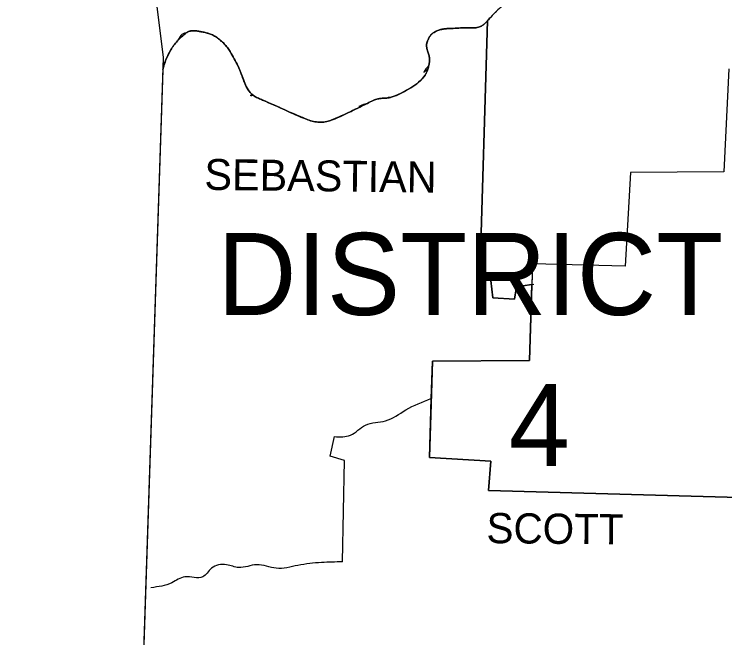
# Model space of a CAD drawing. Extents: x -13171 to 18763, y -8840 to 11152.
# Drawn here: x 10745 to 11711, y 7898 to 8746 of the extents above; entities that cross this region are included whole.
import ezdxf

# ---------------------------------------------------------------- set-up
doc = ezdxf.new("R2010")
doc.units = 0
for name, color, linetype in [('Level 1', 7, 'Continuous'), ('Level 2', 7, 'Continuous'), ('Level 3', 7, 'Continuous'), ('Level 48', 7, 'Continuous')]:
    doc.layers.add(name, color=color, linetype=linetype)

msp = doc.modelspace()

# ---------------------------------------------------------------- linework, layer by layer
at = {"layer": 'Level 1'}
msp.add_line((11311.888127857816, 8223.111308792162), (11312.3324662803, 8223.320542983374), dxfattribs=at)
for points in [[(10745.390580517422, 10312.988270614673), (10947.920791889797, 8686.876140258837), (10859.864178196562, 6032.458444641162)], [(11388.567808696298, 8736.575450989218), (11378.419791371, 8387.483654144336), (11393.095893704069, 8383.570026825), (11396.031114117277, 8360.08826321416), (11425.383318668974, 8358.131449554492), (11428.318539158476, 8374.764365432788), (11451.80030269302, 8378.67799267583)], [(11716.948550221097, 8671.221631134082), (11710.099702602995, 8531.309456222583), (11582.906816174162, 8530.331049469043), (11576.057968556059, 8403.138163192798), (11449.843489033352, 8406.073383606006), (11445.929861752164, 8274.966870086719), (11313.844941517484, 8273.988463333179), (11309.931314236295, 8142.881949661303), (11393.095893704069, 8137.989915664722), (11390.160673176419, 8097.875236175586), (11827.900316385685, 8085.771835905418)], [(11191.544089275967, 8001.0129612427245), (11194.479309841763, 8138.9683225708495), (11174.91117343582, 8144.838763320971), (11180.781614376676, 8171.255747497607)]]:
    msp.add_lwpolyline(points, dxfattribs=at)
for points in [[(11454.735523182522, 8917.780149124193), (11455.612357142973, 8912.663859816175), (11455.98488757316, 8907.452184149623), (11454.735523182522, 8897.233606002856), (11452.950627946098, 8891.815859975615), (11450.895159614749, 8886.475128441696), (11448.803059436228, 8881.13239818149), (11446.908268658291, 8875.70865597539), (11442.016234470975, 8857.118926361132), (11442.023444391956, 8851.055816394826), (11443.52192513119, 8844.908468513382), (11445.001365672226, 8838.75130696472), (11445.261973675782, 8835.692303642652), (11444.951454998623, 8832.658755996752), (11441.344939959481, 8822.595474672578), (11436.145793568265, 8813.090619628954), (11433.14169039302, 8808.983337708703), (11429.65109198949, 8805.249909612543), (11426.228022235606, 8801.523209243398), (11423.426505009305, 8797.436110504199), (11422.612506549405, 8792.784643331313), (11423.493055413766, 8787.660128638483), (11424.340329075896, 8782.531570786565), (11423.426505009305, 8777.867974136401), (11421.86730924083, 8775.122246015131), (11420.243552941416, 8772.4075669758), (11416.774155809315, 8767.110635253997), (11412.961907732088, 8762.055737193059), (11408.750402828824, 8757.321431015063), (11393.095893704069, 8741.666921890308), (11386.858936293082, 8734.618487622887), (11383.480516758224, 8731.392237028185), (11381.552216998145, 8730.044901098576), (11380.506531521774, 8729.461592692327), (11379.398198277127, 8728.94763340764), (11373.352562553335, 8727.29911046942), (11367.233335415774, 8726.893252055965), (11361.081497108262, 8727.02538090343), (11358.006155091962, 8727.072978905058), (11354.938027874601, 8726.990819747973), (11344.665047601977, 8726.513200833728), (11334.391484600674, 8726.012412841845), (11329.067462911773, 8725.490061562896), (11323.889080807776, 8724.384519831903), (11318.82526482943, 8722.38071269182), (11316.326608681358, 8720.943498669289), (11313.844941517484, 8719.163565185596), (11310.609534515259, 8715.935386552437), (11308.365609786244, 8712.349359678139), (11306.904537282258, 8708.501409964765), (11306.017686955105, 8704.487462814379), (11306.256050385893, 8698.874063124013), (11307.898550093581, 8693.225334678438), (11309.579025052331, 8687.581831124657), (11309.931314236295, 8681.984106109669), (11309.018511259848, 8676.43069044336), (11307.614201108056, 8670.957855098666), (11302.104059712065, 8660.459156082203), (11292.458280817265, 8650.956737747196), (11281.557516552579, 8643.826240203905), (11270.524128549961, 8637.809323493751), (11259.054159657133, 8633.063765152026), (11253.2193963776, 8631.832798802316), (11247.203108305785, 8631.353586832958), (11241.241904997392, 8630.7510571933), (11235.572396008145, 8629.15013783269), (11227.440015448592, 8625.385856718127), (11219.402375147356, 8621.412684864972), (11211.377889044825, 8617.394612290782), (11203.284971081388, 8613.49562901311), (11173.932766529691, 8600.776340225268), (11166.283379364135, 8598.962229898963), (11158.23528129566, 8598.846966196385), (11150.208671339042, 8600.185592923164), (11142.62374850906, 8602.733153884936), (11113.271543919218, 8615.452442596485), (11086.854559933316, 8627.193324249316), (11081.360377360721, 8629.498790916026), (11075.895197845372, 8631.906088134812), (11070.77306355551, 8634.892223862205), (11068.438776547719, 8636.751421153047), (11067.345502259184, 8637.798638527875), (11066.30801665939, 8638.934206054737), (11060.75323199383, 8647.416196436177), (11056.896773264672, 8656.60846252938), (11053.587707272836, 8666.013863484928), (11051.778779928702, 8670.641133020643), (11049.675100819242, 8675.135258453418), (11044.466597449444, 8684.975578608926), (11038.912625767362, 8694.703394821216), (11035.152842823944, 8700.255734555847), (11030.870011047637, 8705.305141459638), (11025.961054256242, 8709.945709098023), (11023.239567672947, 8712.142082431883), (11020.322896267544, 8714.271531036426), (11014.883142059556, 8717.379374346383), (11009.27083741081, 8719.504022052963), (11003.558723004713, 8720.969237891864), (10997.819539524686, 8722.098785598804), (10993.203239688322, 8722.872284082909), (10988.454518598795, 8723.159201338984), (10983.74087555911, 8722.426707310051), (10981.449551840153, 8721.511671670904), (10979.22980987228, 8720.141971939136), (10967.173548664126, 8709.249197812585), (10958.160238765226, 8697.140161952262), (10951.715223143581, 8684.01835777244), (10949.307495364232, 8677.141259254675), (10947.363844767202, 8670.087278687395)], [(11180.781614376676, 8171.255747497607), (11202.306564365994, 8173.212561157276), (11222.853107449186, 8186.910256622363), (11250.248498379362, 8192.78069744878), (11277.64388927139, 8207.456799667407), (11311.888127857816, 8223.111308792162)], [(11191.544089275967, 8001.0129612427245), (11163.170291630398, 8000.034554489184), (11130.882866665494, 7996.120927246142), (11101.530662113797, 7992.207299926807), (11075.113678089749, 7997.099333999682), (11050.65350757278, 7993.185706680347), (11034.020591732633, 7997.099333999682), (11013.474048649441, 7992.207299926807), (11001.733166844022, 7980.466418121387), (10977.27299625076, 7980.466418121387), (10959.66167354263, 7972.639163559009), (10931.287875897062, 7965.7903157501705)]]:
    msp.add_spline(points, degree=3, dxfattribs=at)
at = {"layer": 'Level 48'}
for p, q in [((11393.09589370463, 8741.666921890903), (11396.970801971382, 8745.614881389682)), ((11396.970801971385, 8745.614881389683), (11400.921270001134, 8749.491502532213)), ((11388.566359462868, 8736.525597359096), (11386.858936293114, 8734.618487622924)), ((11389.202136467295, 8737.260691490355), (11390.988122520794, 8739.334822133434)), ((10983.74087555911, 8722.426707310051), (10982.273637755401, 8721.90200086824)), ((10983.830943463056, 8722.45219376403), (10983.74087555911, 8722.426707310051)), ((10990.764458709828, 8723.116008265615), (10988.454518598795, 8723.159201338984)), ((10994.277470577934, 8722.704073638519), (10993.987864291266, 8722.749878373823)), ((11344.665047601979, 8726.51320083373), (11339.925173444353, 8726.285509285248)), ((11014.910015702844, 8717.366704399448), (11014.883142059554, 8717.379374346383)), ((11023.239567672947, 8712.142082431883), (11021.771207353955, 8713.24507731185)), ((11313.500243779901, 8718.882213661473), (11311.456950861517, 8716.921028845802)), ((11313.844941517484, 8719.163565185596), (11313.500243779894, 8718.882213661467)), ((11315.146004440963, 8720.145754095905), (11313.844941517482, 8719.163565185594)), ((11025.961054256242, 8709.945709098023), (11024.1626761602, 8711.41853658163)), ((11026.320892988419, 8709.638042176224), (11025.961054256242, 8709.945709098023)), ((11034.476175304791, 8701.145001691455), (11031.248327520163, 8704.908589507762)), ((11306.66476992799, 8707.68224713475), (11306.034421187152, 8704.62108130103)), ((10958.160238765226, 8697.140161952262), (10951.715223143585, 8684.018357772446)), ((10958.229654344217, 8697.259020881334), (10958.160238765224, 8697.14016195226)), ((11035.152842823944, 8700.255734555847), (11034.476175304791, 8701.145001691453)), ((11305.861066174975, 8701.63320490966), (11305.957197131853, 8700.355582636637)), ((10951.715223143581, 8684.01835777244), (10949.830139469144, 8678.83229983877)), ((10947.3638447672, 8670.087278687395), (10913.67835443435, 7654.656888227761)), ((11055.218795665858, 8661.405318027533), (11054.050759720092, 8664.742938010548)), ((11068.438776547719, 8636.751421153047), (11067.345502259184, 8637.798638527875)), ((11281.557516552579, 8643.826240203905), (11270.524128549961, 8637.809323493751)), ((11227.440015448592, 8625.385856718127), (11227.31857751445, 8625.325954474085)), ((11237.412740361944, 8629.86321686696), (11236.800737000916, 8629.64627560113)), ((11241.241904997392, 8630.7510571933), (11237.412740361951, 8629.863216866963)), ((11247.203108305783, 8631.353586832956), (11241.820288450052, 8630.82033611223)), ((11253.21939637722, 8631.832798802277), (11247.203108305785, 8631.353586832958)), ((11259.054159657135, 8633.063765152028), (11256.932204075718, 8632.46590624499)), ((11219.402375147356, 8621.412684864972), (11219.262333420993, 8621.342881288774)), ((11204.547430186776, 8614.097472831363), (11203.284971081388, 8613.49562901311)), ((11160.667378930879, 8598.700472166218), (11160.074025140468, 8598.722407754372)), ((11166.283379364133, 8598.962229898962), (11160.66737893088, 8598.70047216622)), ((11396.031114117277, 8360.08826321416), (11393.095893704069, 8383.570026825)), ((11449.011843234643, 8378.213249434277), (11428.318539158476, 8374.764365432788)), ((11449.011843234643, 8378.213249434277), (11445.929861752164, 8274.966870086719))]:
    msp.add_line(p, q, dxfattribs=at)
for points in [[(10883.435220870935, 9204.629854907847), (10947.920791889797, 8686.876140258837), (10947.3638447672, 8670.087278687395)], [(11393.095893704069, 8383.570026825), (11378.419791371, 8387.483654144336), (11388.56635946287, 8736.525597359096)], [(11716.948550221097, 8671.221631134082), (11710.099702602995, 8531.309456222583), (11582.906816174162, 8530.331049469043), (11576.057968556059, 8403.138163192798), (11449.843489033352, 8406.073383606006), (11449.011843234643, 8378.213249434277)], [(11827.900316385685, 8085.771835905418), (11390.160673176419, 8097.875236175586), (11393.095893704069, 8137.989915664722), (11309.931314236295, 8142.881949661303), (11312.325830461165, 8223.098243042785), (11313.844941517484, 8273.988463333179), (11445.929861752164, 8274.966870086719), (11449.011843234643, 8378.213249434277)], [(11428.318539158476, 8374.764365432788), (11425.383318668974, 8358.131449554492), (11396.031114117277, 8360.08826321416)], [(11445.929861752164, 8274.966870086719), (11313.844941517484, 8273.988463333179), (11312.325830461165, 8223.098243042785), (11309.931314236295, 8142.881949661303), (11393.095893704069, 8137.989915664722)], [(11393.095893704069, 8137.989915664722), (11390.160673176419, 8097.875236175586), (11827.900316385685, 8085.771835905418)]]:
    msp.add_lwpolyline(points, dxfattribs=at)
for points in [[(11390.988122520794, 8739.334822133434), (11393.095893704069, 8741.666921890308), (11393.095893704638, 8741.666921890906)], [(11256.932204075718, 8632.46590624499), (11259.054159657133, 8633.063765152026), (11270.524128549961, 8637.809323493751), (11281.557516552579, 8643.826240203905), (11292.458280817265, 8650.956737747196), (11302.104059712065, 8660.459156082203), (11307.614201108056, 8670.957855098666), (11309.018511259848, 8676.43069044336), (11309.931314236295, 8681.984106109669), (11309.579025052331, 8687.581831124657), (11307.898550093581, 8693.225334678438), (11306.256050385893, 8698.874063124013), (11306.017686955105, 8704.487462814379), (11306.904537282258, 8708.501409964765), (11308.365609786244, 8712.349359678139), (11310.609534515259, 8715.935386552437), (11313.844941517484, 8719.163565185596), (11316.326608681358, 8720.943498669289), (11318.82526482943, 8722.38071269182), (11323.889080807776, 8724.384519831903), (11329.067462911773, 8725.490061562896), (11334.391484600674, 8726.012412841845), (11344.665047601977, 8726.513200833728), (11354.938027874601, 8726.990819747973), (11358.006155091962, 8727.072978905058), (11361.081497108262, 8727.02538090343), (11367.233335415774, 8726.893252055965), (11373.352562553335, 8727.29911046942), (11379.398198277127, 8728.94763340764), (11380.506531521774, 8729.461592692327), (11381.552216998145, 8730.044901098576), (11383.480516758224, 8731.392237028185), (11386.858936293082, 8734.618487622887), (11388.566359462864, 8736.525597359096)], [(10947.363844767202, 8670.087278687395), (10949.307495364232, 8677.141259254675), (10951.715223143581, 8684.01835777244), (10958.160238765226, 8697.140161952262), (10967.173548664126, 8709.249197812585), (10979.22980987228, 8720.141971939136), (10981.449551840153, 8721.511671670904), (10983.74087555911, 8722.426707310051), (10988.454518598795, 8723.159201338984), (10993.203239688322, 8722.872284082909), (10997.819539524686, 8722.098785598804), (11003.558723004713, 8720.969237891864), (11009.27083741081, 8719.504022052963), (11014.883142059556, 8717.379374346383), (11020.322896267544, 8714.271531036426), (11023.239567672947, 8712.142082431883), (11025.961054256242, 8709.945709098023), (11030.870011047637, 8705.305141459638), (11035.152842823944, 8700.255734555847), (11038.912625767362, 8694.703394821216), (11044.466597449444, 8684.975578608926), (11049.675100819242, 8675.135258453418), (11051.778779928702, 8670.641133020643), (11053.587707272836, 8666.013863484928), (11056.896773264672, 8656.60846252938), (11060.75323199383, 8647.416196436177), (11066.30801665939, 8638.934206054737), (11067.345502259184, 8637.798638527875), (11068.438776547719, 8636.751421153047), (11070.77306355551, 8634.892223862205), (11071.161602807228, 8634.624828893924)], [(10993.987864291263, 8722.749878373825), (10993.203239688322, 8722.872284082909), (10990.76445870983, 8723.116008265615)], [(10979.22980987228, 8720.141971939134), (10979.22980987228, 8720.141971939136), (10967.173548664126, 8709.249197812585)], [(11004.426463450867, 8720.780023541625), (11003.558723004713, 8720.969237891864), (10999.290877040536, 8721.820989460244)], [(11309.018511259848, 8676.43069044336), (11307.614201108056, 8670.957855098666), (11307.614201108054, 8670.957855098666)], [(11070.607308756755, 8635.008595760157), (11068.438776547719, 8636.751421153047), (11068.438776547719, 8636.751421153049)], [(11270.524128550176, 8637.809323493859), (11270.524128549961, 8637.809323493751), (11261.881585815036, 8634.031948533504)], [(11071.161602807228, 8634.624828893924), (11075.895197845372, 8631.906088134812), (11081.360377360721, 8629.498790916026), (11086.854559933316, 8627.193324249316), (11113.271543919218, 8615.452442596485), (11142.62374850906, 8602.733153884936), (11150.208671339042, 8600.185592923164), (11158.23528129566, 8598.846966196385), (11166.283379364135, 8598.962229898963), (11173.932766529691, 8600.776340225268), (11203.284971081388, 8613.49562901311), (11211.377889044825, 8617.394612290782), (11219.402375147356, 8621.412684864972), (11227.440015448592, 8625.385856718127), (11235.572396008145, 8629.15013783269), (11241.241904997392, 8630.7510571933), (11247.203108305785, 8631.353586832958), (11253.2193963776, 8631.832798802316), (11256.932204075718, 8632.46590624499)], [(11075.895197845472, 8631.906088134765), (11075.895197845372, 8631.906088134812), (11071.161602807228, 8634.624828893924)], [(11081.261480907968, 8629.540647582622), (11075.895197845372, 8631.906088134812), (11075.895197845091, 8631.906088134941)], [(11241.82027800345, 8630.820427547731), (11241.241904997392, 8630.7510571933), (11241.24190499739, 8630.751057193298)], [(11256.932204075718, 8632.46590624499), (11253.2193963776, 8631.832798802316), (11253.219396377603, 8631.832798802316)], [(11261.88158581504, 8634.031948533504), (11259.054159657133, 8633.063765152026), (11259.054159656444, 8633.06376515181)], [(11227.31857751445, 8625.325954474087), (11219.402375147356, 8621.412684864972), (11219.402375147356, 8621.412684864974)]]:
    msp.add_spline(points, degree=3, dxfattribs=at)
for points, degree in [([(11386.858936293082, 8734.618487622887), (11385.811639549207, 8733.46457362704), (11384.683578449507, 8732.396329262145), (11383.480516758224, 8731.392237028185), (11382.87469825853, 8730.886612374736), (11382.226084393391, 8730.451092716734), (11381.552216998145, 8730.044901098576), (11381.209213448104, 8729.838146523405), (11380.861614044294, 8729.646692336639), (11380.506531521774, 8729.461592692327)], 3), ([(11388.566359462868, 8736.525597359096), (11388.779045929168, 8736.770009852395), (11388.990815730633, 8737.01517928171), (11389.202136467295, 8737.260691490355)], 2), ([(10988.454518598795, 8723.159201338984), (10986.900491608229, 8723.14464158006), (10985.361633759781, 8722.882017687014), (10983.830943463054, 8722.452193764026)], 2), ([(10999.290877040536, 8721.820989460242), (10998.800822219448, 8721.914695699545), (10998.310407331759, 8722.007231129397), (10997.819539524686, 8722.098785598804), (10996.640799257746, 8722.31863896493), (10995.461191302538, 8722.516061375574), (10994.277470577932, 8722.704073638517)], 3), ([(11322.981121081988, 8724.103617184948), (11321.55252969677, 8723.635667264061), (11320.175588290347, 8723.060787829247), (11318.82526482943, 8722.38071269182), (11318.223869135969, 8722.077826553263), (11317.644026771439, 8721.753052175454), (11317.073130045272, 8721.408242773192)], 3), ([(11325.439122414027, 8724.803957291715), (11324.921141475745, 8724.675162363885), (11324.404738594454, 8724.534774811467), (11323.889080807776, 8724.384519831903), (11323.583990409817, 8724.295621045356), (11323.281414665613, 8724.201981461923), (11322.981121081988, 8724.103617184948)], 3), ([(11339.925173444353, 8726.285509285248), (11338.080583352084, 8726.195489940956), (11336.236056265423, 8726.104119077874), (11334.391484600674, 8726.012412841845), (11332.610443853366, 8725.923865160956), (11330.839998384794, 8725.710798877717), (11329.067462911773, 8725.490061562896), (11327.842717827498, 8725.337541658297), (11326.636702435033, 8725.101733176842), (11325.439122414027, 8724.803957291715)], 3), ([(11354.938027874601, 8726.990819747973), (11351.51293668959, 8726.835016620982), (11348.089313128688, 8726.6746132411), (11344.665047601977, 8726.513200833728)], 2), ([(11356.118650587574, 8727.039846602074), (11355.72502410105, 8727.02585787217), (11355.331466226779, 8727.008716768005), (11354.938027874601, 8726.990819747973)], 2), ([(11361.081497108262, 8727.02538090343), (11360.056395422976, 8727.043246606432), (11359.031236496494, 8727.067231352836), (11358.006155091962, 8727.072978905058), (11357.3769502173, 8727.076506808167), (11356.747712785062, 8727.062202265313), (11356.118650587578, 8727.039846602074)], 3), ([(11367.06802081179, 8726.896414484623), (11365.072535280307, 8726.935063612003), (11363.077201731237, 8726.99059931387), (11361.081497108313, 8727.02538090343)], 2), ([(11380.133985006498, 8729.274569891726), (11379.893221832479, 8729.158381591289), (11379.649308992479, 8729.049785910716), (11379.398198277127, 8728.94763340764), (11377.442343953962, 8728.151986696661), (11375.434498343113, 8727.584323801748), (11373.352562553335, 8727.29911046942), (11371.315045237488, 8727.019982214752), (11369.277074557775, 8726.854653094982), (11367.233335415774, 8726.893252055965), (11367.17823042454, 8726.894292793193), (11367.123125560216, 8726.895347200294), (11367.06802081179, 8726.896414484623)], 3), ([(11380.506531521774, 8729.461592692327), (11380.382819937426, 8729.397103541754), (11380.258825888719, 8729.334816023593), (11380.133985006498, 8729.274569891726)], 2), ([(10982.273637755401, 8721.902000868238), (10981.996616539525, 8721.782277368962), (10981.72296307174, 8721.652225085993), (10981.449551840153, 8721.511671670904), (10980.665944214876, 8721.108839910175), (10979.93665003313, 8720.666653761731), (10979.22980987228, 8720.141971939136)], 3), ([(11009.975086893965, 8719.293036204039), (11009.7412778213, 8719.365653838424), (11009.506543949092, 8719.435984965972), (11009.27083741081, 8719.504022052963), (11007.662321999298, 8719.968322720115), (11006.054293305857, 8720.410750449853), (11004.426463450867, 8720.780023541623)], 3), ([(11014.883142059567, 8717.379374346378), (11014.883142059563, 8717.37937434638), (11014.88314205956, 8717.379374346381), (11014.883142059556, 8717.379374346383), (11013.282951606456, 8718.133139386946), (11011.65282846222, 8718.771954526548), (11009.975086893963, 8719.293036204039)], 3), ([(11021.771207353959, 8713.245077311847), (11021.293832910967, 8713.592992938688), (11020.811433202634, 8713.934625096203), (11020.322896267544, 8714.271531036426), (11018.60568972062, 8715.455754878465), (11016.803572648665, 8716.47317153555), (11014.910015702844, 8717.366704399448)], 3), ([(11308.365609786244, 8712.349359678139), (11307.772733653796, 8711.093881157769), (11307.31425945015, 8709.829335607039), (11306.904537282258, 8708.501409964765), (11306.820397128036, 8708.228708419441), (11306.74032335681, 8707.955691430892), (11306.664769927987, 8707.682247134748)], 3), ([(11310.609534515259, 8715.935386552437), (11309.704850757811, 8714.822542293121), (11308.974938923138, 8713.639679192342), (11308.365609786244, 8712.349359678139)], 2), ([(11311.456950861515, 8716.921028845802), (11311.167177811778, 8716.60281531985), (11310.885179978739, 8716.274455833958), (11310.609534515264, 8715.935386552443)], 2), ([(11317.073130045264, 8721.408242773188), (11316.822925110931, 8721.257124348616), (11316.574438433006, 8721.102157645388), (11316.326608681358, 8720.943498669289), (11315.92446145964, 8720.686046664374), (11315.531894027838, 8720.420667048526), (11315.146004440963, 8720.145754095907)], 3), ([(10967.173548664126, 8709.249197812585), (10963.770652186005, 8705.509767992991), (10960.773110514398, 8701.603051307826), (10958.229654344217, 8697.259020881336)], 2), ([(11024.1626761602, 8711.41853658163), (11023.856731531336, 8711.66144533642), (11023.549013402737, 8711.902407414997), (11023.239567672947, 8712.142082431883)], 2), ([(11031.248327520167, 8704.908589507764), (11031.12300360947, 8705.04133591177), (11030.996901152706, 8705.17351638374), (11030.870011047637, 8705.305141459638), (11029.410762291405, 8706.818842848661), (11027.908411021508, 8708.269007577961), (11026.320892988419, 8709.638042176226)], 3), ([(11306.034421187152, 8704.621081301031), (11306.02868362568, 8704.576563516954), (11306.023104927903, 8704.532024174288), (11306.017686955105, 8704.487462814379), (11305.903994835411, 8703.552375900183), (11305.835195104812, 8702.589619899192), (11305.861066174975, 8701.63320490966)], 3), ([(11038.912625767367, 8694.70339482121), (11038.912625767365, 8694.703394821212), (11038.912625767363, 8694.703394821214), (11038.912625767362, 8694.703394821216), (11037.768805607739, 8696.627274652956), (11036.492423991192, 8698.455844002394), (11035.152842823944, 8700.255734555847)], 3), ([(11044.466597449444, 8684.975578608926), (11042.677661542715, 8688.255501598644), (11040.823381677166, 8691.489546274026), (11038.912625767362, 8694.703394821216)], 2), ([(11305.957197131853, 8700.35558263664), (11306.021293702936, 8699.853950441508), (11306.118421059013, 8699.358409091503), (11306.256050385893, 8698.874063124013), (11306.744979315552, 8697.15342144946), (11307.246740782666, 8695.44071692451), (11307.750881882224, 8693.727105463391)], 3), ([(11307.750881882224, 8693.727105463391), (11307.800085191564, 8693.559859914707), (11307.849311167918, 8693.39260572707), (11307.898550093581, 8693.225334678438), (11308.452832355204, 8691.342365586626), (11309.030542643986, 8689.473803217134), (11309.579025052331, 8687.581831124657), (11309.733977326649, 8687.047328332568), (11309.844335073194, 8686.500335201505), (11309.918076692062, 8685.946973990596)], 3), ([(11051.453355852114, 8671.396842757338), (11050.8985711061, 8672.66096954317), (11050.301373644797, 8673.904290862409), (11049.675100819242, 8675.135258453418), (11047.990823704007, 8678.445781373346), (11046.244689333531, 8681.715537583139), (11044.466597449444, 8684.975578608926)], 3), ([(11309.918076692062, 8685.946973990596), (11310.092963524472, 8684.634613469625), (11310.061900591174, 8683.286435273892), (11309.931314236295, 8681.984106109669), (11309.84562005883, 8681.1294836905), (11309.727472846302, 8680.276811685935), (11309.587201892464, 8679.425337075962)], 3), ([(10949.830139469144, 8678.832299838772), (10949.647233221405, 8678.271789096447), (10949.472368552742, 8677.708431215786), (10949.307495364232, 8677.141259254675), (10948.626032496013, 8674.79699312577), (10947.939073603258, 8672.457426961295), (10947.363844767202, 8670.087278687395)], 3), ([(11309.587201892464, 8679.425337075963), (11309.422552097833, 8678.425877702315), (11309.22742016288, 8677.428068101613), (11309.018511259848, 8676.43069044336)], 2), ([(11054.050759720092, 8664.742938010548), (11053.898448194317, 8665.167267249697), (11053.744301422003, 8665.590975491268), (11053.587707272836, 8666.013863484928), (11053.012534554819, 8667.567137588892), (11052.423724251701, 8669.113745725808), (11051.778779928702, 8670.641133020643), (11051.672047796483, 8670.893901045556), (11051.56353827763, 8671.145782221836), (11051.453355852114, 8671.396842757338)], 3), ([(11307.614201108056, 8670.957855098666), (11306.410993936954, 8667.159144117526), (11304.561916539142, 8663.704587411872), (11302.104059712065, 8660.459156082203), (11299.29724867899, 8656.752954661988), (11296.155441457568, 8653.617002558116), (11292.458280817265, 8650.956737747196), (11289.415031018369, 8648.76698968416), (11286.35448179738, 8646.709973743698), (11283.176534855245, 8644.78768730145)], 3), ([(11058.225216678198, 8653.141028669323), (11057.76158514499, 8654.287854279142), (11057.319273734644, 8655.443077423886), (11056.896773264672, 8656.60846252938), (11056.319127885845, 8658.201784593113), (11055.770617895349, 8659.804257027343), (11055.21879566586, 8661.40531802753)], 3), ([(11067.345502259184, 8637.798638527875), (11066.983101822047, 8638.163117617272), (11066.63901627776, 8638.537928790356), (11066.30801665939, 8638.934206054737), (11064.126159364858, 8641.5463554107), (11062.225429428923, 8644.35095084), (11060.75323199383, 8647.416196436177), (11059.845435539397, 8649.306309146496), (11059.00515867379, 8651.211786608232), (11058.225216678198, 8653.141028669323)], 3), ([(11283.176534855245, 8644.78768730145), (11282.640364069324, 8644.463366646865), (11282.100851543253, 8644.142881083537), (11281.557516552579, 8643.826240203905)], 2), ([(11071.161602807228, 8634.624828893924), (11071.031650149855, 8634.71331842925), (11070.902286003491, 8634.80259752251), (11070.77306355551, 8634.892223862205), (11070.717579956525, 8634.930706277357), (11070.662332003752, 8634.969501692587), (11070.607308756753, 8635.008595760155)], 3), ([(11086.849366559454, 8627.195587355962), (11085.030369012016, 8627.98818652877), (11083.18810776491, 8628.725886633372), (11081.360377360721, 8629.498790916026), (11081.32740678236, 8629.512733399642), (11081.294441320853, 8629.526685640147), (11081.261480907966, 8629.540647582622)], 3), ([(11113.271543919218, 8615.452442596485), (11104.458148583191, 8619.350029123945), (11095.688198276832, 8623.343605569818), (11086.854559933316, 8627.193324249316), (11086.852828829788, 8627.194078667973), (11086.851097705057, 8627.194833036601), (11086.849366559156, 8627.195587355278)], 3), ([(11236.800737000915, 8629.646275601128), (11236.386748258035, 8629.492697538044), (11235.9770923, 8629.326898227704), (11235.572396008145, 8629.15013783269), (11232.820093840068, 8627.948006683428), (11230.119143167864, 8626.707479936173), (11227.440015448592, 8625.385856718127)], 3), ([(11219.262333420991, 8621.342881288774), (11216.631852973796, 8620.031410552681), (11214.008468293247, 8618.706103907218), (11211.377889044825, 8617.394612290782), (11209.115070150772, 8616.26646988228), (11206.83083313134, 8615.184370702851), (11204.547430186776, 8614.097472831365)], 3), ([(11150.208671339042, 8600.185592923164), (11147.609439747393, 8600.90877764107), (11145.078168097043, 8601.683789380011), (11142.62374850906, 8602.733153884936), (11132.810890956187, 8606.928550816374), (11123.024246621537, 8611.139462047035), (11113.271543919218, 8615.452442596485)], 3), ([(11203.284971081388, 8613.49562901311), (11193.659306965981, 8608.896939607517), (11183.943053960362, 8604.759817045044), (11173.932766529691, 8600.776340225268), (11171.472699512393, 8599.797385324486), (11168.889819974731, 8599.293166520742), (11166.283379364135, 8598.962229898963)], 3), ([(11160.074025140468, 8598.722407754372), (11159.459500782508, 8598.749789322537), (11158.846236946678, 8598.791549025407), (11158.23528129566, 8598.846966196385), (11155.538169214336, 8599.091609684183), (11152.852130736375, 8599.450102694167), (11150.208671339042, 8600.185592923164)], 3)]:
    msp.add_open_spline(points, degree=degree, dxfattribs=at)

# ---------------------------------------------------------------- texts
at = {"layer": 'Level 2'}
for s, height, rotation, p in [('SEBASTIAN', 42.06170907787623, 359.2815944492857, (11003.689980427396, 8506.84928578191)), ('SCOTT', 41.09308632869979, 359.4062833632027, (11387.225452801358, 8026.451538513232))]:
    msp.add_text(s, height=height, rotation=rotation, dxfattribs=at).set_placement(p)
at = {"layer": 'Level 3'}
for s, p in [('DISTRICT', (11021.301303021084, 8336.60649960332)), ('4', (11417.556064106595, 8131.141068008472))]:
    msp.add_text(s, height=111.53837717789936, dxfattribs=at).set_placement(p)

doc.saveas('drawing.dxf')
